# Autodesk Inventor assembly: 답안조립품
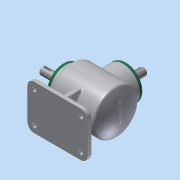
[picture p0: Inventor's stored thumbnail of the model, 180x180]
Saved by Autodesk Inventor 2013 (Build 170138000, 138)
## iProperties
Created: 2016-09
Part Number: 답안조립품
Document SubType Name: Assembly
Designer: Administrator
Author: Administrator
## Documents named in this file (14)
- C:\Users\Administrator\Desktop\460907V1012\답안조립품.iam
- C:\Users\Administrator\Desktop\460907V1012\본체.ipt
- C:\Users\Administrator\Desktop\460907V1012\커버.ipt
- C:\Users\Administrator\Desktop\460907V1012\오일실 17 32 8.ipt
- C:\Users\Administrator\Desktop\460907V1012\M4.ipt
- C:\Users\Administrator\Desktop\460907V1012\베어링 6203.ipt
- C:\Users\Administrator\Desktop\460907V1012\메인 축.ipt
- 메인 축.ipt
- C:\Users\Administrator\Desktop\460907V1012\키 5x5.ipt
- C:\Users\Administrator\Desktop\460907V1012\메인 베벨기어.ipt
- C:\Users\Administrator\Desktop\460907V1012\서브 축.ipt
- 서브 축.ipt
- C:\Users\Administrator\Desktop\460907V1012\키 4x4.ipt
- C:\Users\Administrator\Desktop\460907V1012\서브 베벨기어.ipt
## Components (8 placed, 1 different names)
1. M4:1
2. M4:3
3. M4:4
4. M4:5
5. M4:2
6. M4:6
7. M4:7
8. M4:8
